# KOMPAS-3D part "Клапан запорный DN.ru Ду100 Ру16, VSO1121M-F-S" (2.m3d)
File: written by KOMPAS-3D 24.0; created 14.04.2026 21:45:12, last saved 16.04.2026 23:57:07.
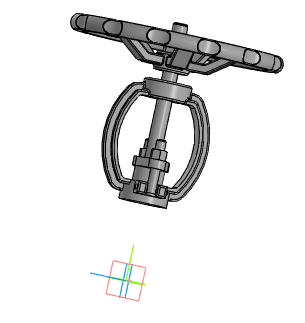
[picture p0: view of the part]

Document properties: Автор: R2D2; Полное имя файла: E:\Работа\Зайцев\VSO3131M-F-S Клапан запорный DN.ru Ду15-100 Ру16\DN100\исходные материалы\2.m3d

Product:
- Part/product: Клапан запорный DN.ru Ду100 Ру16  | designation VSO1121M-F-S
    Масса: 38.27
    Раздел спецификации: Прочие изделия
    Примечание: D090-01950

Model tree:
1. Операция без истории:1
2. Эскиз:1  (with: Ребро.Операция без истории:1)
3. Элемент вращения:1
     Угол 1 = 360
4. Эскиз:2  (with: Ребро.Операция без истории:1)
5. Элемент выдавливания:1
     Расстояние 1 = 54
6. Зеркальный массив:1
7. Экземпляр ( 1 )
8. Экземпляр ( 2 )  (with: Элемент выдавливания:1)
9. Масштабирование:2
10. Масштабирование : Тело 3
     Масштаб по оси Х = 1; Масштаб по оси Y = 1; Масштаб по оси Z = 1; Коэффициент = 0.9

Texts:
  VSO1121M-F-S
